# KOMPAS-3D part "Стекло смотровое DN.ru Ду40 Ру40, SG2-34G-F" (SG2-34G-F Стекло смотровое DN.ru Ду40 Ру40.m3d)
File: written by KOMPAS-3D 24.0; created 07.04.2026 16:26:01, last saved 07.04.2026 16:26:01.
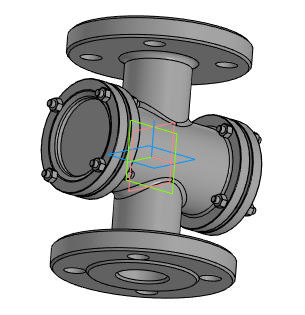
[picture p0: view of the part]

Document properties: Автор: Main; Полное имя файла: D:\DN.ru Аутсерс\Стекло смотровое DN.ru\SG2-34G-F Стекло смотровое DN.ru Ду40 Ру40\SG2-34G-F Стекло смотровое DN.ru Ду40 Ру40.m3d

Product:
- Part/product: Стекло смотровое DN.ru Ду40 Ру40  | designation SG2-34G-F
    Масса: 9
    Раздел спецификации: Прочие изделия
    Примечание: D500-00083

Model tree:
1. Операция без истории:1

Expressions: SG2-34G-F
